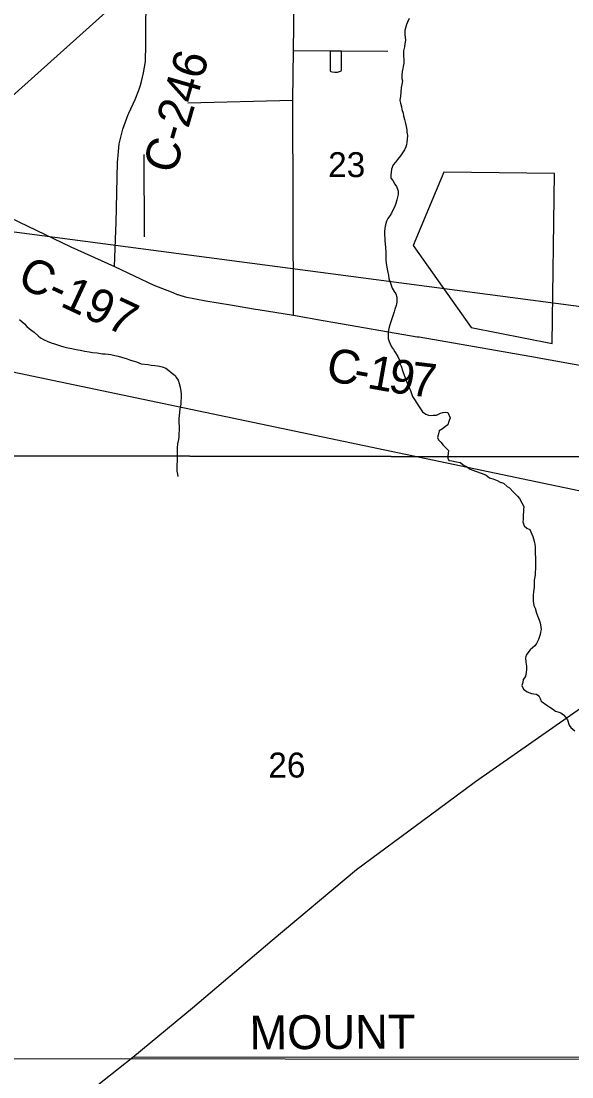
# Model space of a CAD drawing. Extents: x 0 to 34, y 0 to 22.
# Drawn here: x 6.537 to 7.462, y 15.401 to 17.171 of the extents above; entities that cross this region are included whole.
import ezdxf

# ---------------------------------------------------------------- set-up
doc = ezdxf.new("R2010")
doc.units = 0
for name, color, linetype in [('GM_X_City_Street', 7, 'Continuous'), ('GM_X_County_Road', 7, 'Continuous'), ('GM_X_County_Road_Text', 7, 'Continuous'), ('GM_X_Minor_Lake', 7, 'Continuous'), ('GM_X_Minor_River', 7, 'Continuous'), ('GM_X_Rail_Line', 7, 'Continuous'), ('GM_X_Section', 7, 'Continuous'), ('GM_X_Section_Text', 7, 'Continuous'), ('GM_X_Township_Road', 7, 'Continuous'), ('GM_X_Township_Road_Text', 7, 'Continuous'), ('SH_Data', 7, 'Continuous')]:
    doc.layers.add(name, color=color, linetype=linetype)

msp = doc.modelspace()

# ---------------------------------------------------------------- linework, layer by layer
at = {"layer": 'GM_X_City_Street'}
for p, q in [((6.817, 17.0337), (6.9929, 17.0382)), ((6.7444, 16.8095), (6.7437, 16.9474))]:
    msp.add_line(p, q, dxfattribs=at)
for points in [[(6.994, 17.1215), (7.0557, 17.1213), (7.0747, 17.1212), (7.1527, 17.1208)], [(7.0557, 17.1213), (7.0556, 17.0874), (7.0568, 17.0867), (7.0593, 17.0859), (7.0636, 17.0851), (7.068, 17.0852), (7.0733, 17.0868), (7.0741, 17.0875), (7.0746, 17.0885), (7.0747, 17.1212)]]:
    msp.add_lwpolyline(points, dxfattribs=at)
at = {"layer": 'GM_X_County_Road'}
for p, q in [((6.6936, 16.7596), (6.6961, 16.8196)), ((6.8036, 16.7112), (6.8126, 16.7084)), ((6.9943, 16.6777), (7.0438, 16.6692)), ((7.0438, 16.6692), (7.0635, 16.6658)), ((7.0635, 16.6658), (7.2021, 16.6418))]:
    msp.add_line(p, q, dxfattribs=at)
for points in [[(6.9943, 16.6777), (6.9929, 17.0382), (6.994, 17.1215), (6.9958, 17.2486), (6.9968, 17.319), (6.9978, 17.387), (7.0072, 17.472), (7, 17.5404)], [(6.7374, 17.0638), (6.7393, 17.0697), (6.7425, 17.084), (6.7456, 17.1033), (6.7462, 17.1319), (6.7464, 17.1706), (6.7473, 17.2079), (6.7515, 17.2415), (6.7604, 17.279), (6.7736, 17.3034), (6.7807, 17.3258), (6.7807, 17.3402), (6.7779, 17.3604), (6.7688, 17.3754), (6.7575, 17.3922)], [(6.6996, 16.9402), (6.7, 16.9456), (6.7016, 16.9651), (6.7078, 16.9898), (6.7168, 17.0144), (6.7178, 17.0166), (6.7283, 17.0397), (6.7345, 17.0549), (6.7374, 17.0638)], [(6.6961, 16.8196), (6.6966, 16.8329), (6.699, 16.9336), (6.6996, 16.9402)], [(6.4994, 16.8506), (6.5042, 16.8482), (6.6203, 16.7926), (6.6936, 16.7596), (6.76, 16.7284), (6.7817, 16.7198), (6.7916, 16.7158), (6.7987, 16.7128), (6.8, 16.7123), (6.8036, 16.7112)], [(6.8126, 16.7084), (6.847, 16.7019), (6.8884, 16.6952), (6.9305, 16.6882)], [(6.9305, 16.6882), (6.9351, 16.6875), (6.9943, 16.6777)], [(7.2021, 16.6418), (7.2051, 16.6413), (7.3908, 16.6094), (7.4995, 16.5896)], [(7.237, 15.8497), (7.2995, 15.8959), (7.4946, 16.032)], [(5.5469, 14.4344), (5.6758, 14.5508), (5.8694, 14.7369), (6.0097, 14.8665), (6.1246, 14.9524), (6.1906, 14.9973), (6.2946, 15.0744), (6.3669, 15.1429), (6.4394, 15.2123), (6.6285, 15.3575), (6.7245, 15.4335), (6.8246, 15.5163), (6.9585, 15.6298), (7.1001, 15.7486), (7.237, 15.8497)]]:
    msp.add_lwpolyline(points, dxfattribs=at)
at = {"layer": 'GM_X_Minor_Lake'}
for p, q in [((7.2464, 16.9179), (7.1952, 16.7947)), ((7.4322, 16.9154), (7.2464, 16.9179)), ((7.4283, 16.6306), (7.4322, 16.9154)), ((7.1952, 16.7947), (7.2924, 16.6572)), ((7.2924, 16.6572), (7.4283, 16.6306))]:
    msp.add_line(p, q, dxfattribs=at)
at = {"layer": 'GM_X_Minor_River'}
for p, q in [((7.4322, 16.9154), (7.4322, 16.9154)), ((7.1952, 16.7947), (7.1952, 16.7947)), ((7.2924, 16.6572), (7.2924, 16.6572)), ((7.4283, 16.6306), (7.4283, 16.6306))]:
    msp.add_line(p, q, dxfattribs=at)
for points in [[(7.1883, 17.1753), (7.1857, 17.1692), (7.1842, 17.1654), (7.1827, 17.1612), (7.1812, 17.1551), (7.1813, 17.1487), (7.1821, 17.1388), (7.1813, 17.1331), (7.1806, 17.1278), (7.1791, 17.1213), (7.1787, 17.1175), (7.1788, 17.1133), (7.1796, 17.1057), (7.1796, 17.1004), (7.1785, 17.0951), (7.1777, 17.0913), (7.1766, 17.0864), (7.1759, 17.0803), (7.1763, 17.0746), (7.1771, 17.0708), (7.176, 17.0647), (7.1752, 17.0594), (7.1745, 17.0514), (7.1738, 17.0453), (7.1727, 17.0377), (7.1739, 17.0335), (7.1754, 17.0271), (7.1762, 17.0229), (7.1781, 17.0165), (7.1789, 17.0119), (7.1804, 17.0062), (7.1824, 16.999), (7.1832, 16.9945), (7.1843, 16.9888), (7.1847, 16.985), (7.1855, 16.9789), (7.1852, 16.9732), (7.1844, 16.9679), (7.1837, 16.9637), (7.183, 16.9599), (7.1807, 16.9553), (7.1739, 16.945), (7.1686, 16.9389), (7.1652, 16.9344), (7.1615, 16.9302), (7.1585, 16.9225), (7.1581, 16.9176), (7.1574, 16.9127), (7.1578, 16.9077), (7.1608, 16.9039)], [(7.1608, 16.9039), (7.1643, 16.8975), (7.1673, 16.8937), (7.1697, 16.8865), (7.1701, 16.8801), (7.169, 16.8759), (7.1678, 16.8713), (7.166, 16.8652), (7.1637, 16.8591), (7.1607, 16.8527), (7.1585, 16.8488), (7.1558, 16.8447), (7.1528, 16.8397), (7.1502, 16.8355), (7.1479, 16.8271), (7.1472, 16.8188), (7.1469, 16.8127), (7.1473, 16.8066), (7.1477, 16.8028), (7.1489, 16.7918), (7.1493, 16.7831), (7.1494, 16.7698), (7.1502, 16.7611), (7.1525, 16.7497), (7.1537, 16.7451), (7.1545, 16.7394), (7.1564, 16.7334), (7.1583, 16.7284), (7.1599, 16.7231), (7.1633, 16.7174), (7.166, 16.7136), (7.1679, 16.708), (7.1679, 16.6996), (7.1665, 16.6943), (7.1646, 16.6878), (7.1635, 16.6832), (7.1597, 16.6734), (7.1579, 16.6669), (7.156, 16.6619), (7.1545, 16.6555), (7.1534, 16.6498), (7.153, 16.6441), (7.1531, 16.6388), (7.155, 16.6338), (7.1565, 16.63), (7.1585, 16.6247), (7.1619, 16.6202), (7.1642, 16.6164), (7.1692, 16.6088), (7.1715, 16.6035), (7.1734, 16.5959), (7.1749, 16.5921), (7.178, 16.5834), (7.1819, 16.5728), (7.1857, 16.5626), (7.1884, 16.5565), (7.1911, 16.5497), (7.1942, 16.5417), (7.1976, 16.5364), (7.2053, 16.5243), (7.2083, 16.5194), (7.211, 16.5156), (7.2163, 16.5118), (7.2209, 16.5103), (7.2247, 16.5099), (7.2285, 16.5103), (7.2342, 16.51), (7.241, 16.5138), (7.2452, 16.5146), (7.249, 16.515), (7.2535, 16.5146), (7.2574, 16.5059), (7.2551, 16.4994), (7.2533, 16.4941), (7.2495, 16.4911), (7.2442, 16.4872), (7.2389, 16.4838), (7.237, 16.4766), (7.2359, 16.4728), (7.2374, 16.4686), (7.2416, 16.4648), (7.2455, 16.4599), (7.2497, 16.4557), (7.2542, 16.4508), (7.2535, 16.4417), (7.2535, 16.4379), (7.2551, 16.4341), (7.26, 16.4334), (7.2676, 16.4319), (7.2741, 16.4308), (7.2805, 16.4259), (7.2844, 16.424), (7.2908, 16.4198), (7.3, 16.4161), (7.3095, 16.4131), (7.3136, 16.4112), (7.3174, 16.4097), (7.3235, 16.4052), (7.3308, 16.4029), (7.3361, 16.4007), (7.3414, 16.3981)], [(6.5342, 16.6707), (6.5426, 16.6632), (6.5468, 16.659), (6.5506, 16.6556), (6.5551, 16.6522), (6.559, 16.6492), (6.5654, 16.6435), (6.5696, 16.6401), (6.5757, 16.6367), (6.5807, 16.6345), (6.5875, 16.6315), (6.5928, 16.63), (6.5982, 16.6281), (6.6031, 16.6266), (6.6088, 16.6248), (6.6156, 16.6233), (6.6221, 16.6218), (6.6293, 16.6203), (6.6362, 16.6192), (6.6438, 16.6177), (6.651, 16.6166), (6.6571, 16.6155), (6.6647, 16.6148), (6.6738, 16.6133), (6.678, 16.6129), (6.6829, 16.6126), (6.6878, 16.6118), (6.6943, 16.6103), (6.7, 16.6092), (6.7057, 16.6077), (6.7152, 16.6044), (6.7205, 16.6025), (6.7266, 16.601), (6.7308, 16.5999), (6.7388, 16.5965), (6.7502, 16.595), (6.7555, 16.5939), (6.7616, 16.5936), (6.7657, 16.5932), (6.7695, 16.5921), (6.7737, 16.5914), (6.7798, 16.5891), (6.7848, 16.5849), (6.7889, 16.5819), (6.7954, 16.5766), (6.7981, 16.5729)], [(6.7981, 16.5729), (6.8004, 16.5691), (6.8023, 16.5634), (6.8039, 16.5569), (6.8051, 16.5501), (6.8055, 16.5459), (6.8059, 16.5395), (6.8051, 16.5338), (6.8052, 16.5288), (6.8037, 16.5208), (6.803, 16.5148), (6.8022, 16.5098), (6.8019, 16.5045), (6.8019, 16.498), (6.8023, 16.4904), (6.8023, 16.4847), (6.802, 16.4802), (6.8016, 16.4745), (6.8013, 16.4692), (6.7998, 16.4623), (6.7987, 16.4555), (6.7987, 16.449), (6.7991, 16.4452), (6.7992, 16.4407), (6.7988, 16.4334), (6.7985, 16.4266), (6.7985, 16.4163), (6.7997, 16.4114), (6.8001, 16.4076)], [(7.3414, 16.3981), (7.3467, 16.3962), (7.3528, 16.3905), (7.3567, 16.3886), (7.3628, 16.3818), (7.3704, 16.3746), (7.3738, 16.3705), (7.3777, 16.3633), (7.3807, 16.3572), (7.3804, 16.3523), (7.3804, 16.3485), (7.38, 16.3428), (7.3797, 16.3356), (7.3793, 16.3314), (7.3816, 16.3249), (7.3858, 16.3208), (7.3908, 16.3185), (7.3962, 16.3068), (7.3973, 16.303), (7.3989, 16.2969), (7.3997, 16.2901), (7.3997, 16.2844), (7.4001, 16.2794), (7.4005, 16.2699), (7.4006, 16.2631), (7.4002, 16.2525), (7.3999, 16.2471), (7.3999, 16.243), (7.3995, 16.2392), (7.3984, 16.2335), (7.3981, 16.2297), (7.3981, 16.2217), (7.397, 16.2141), (7.3967, 16.2084), (7.3967, 16.1985), (7.3975, 16.1913), (7.3998, 16.1864), (7.4021, 16.1784), (7.4052, 16.1708), (7.4079, 16.1636), (7.4087, 16.1587), (7.4099, 16.1511), (7.4091, 16.1461), (7.4084, 16.1423), (7.4054, 16.1343), (7.4024, 16.1275), (7.3994, 16.1237), (7.3952, 16.1202), (7.3914, 16.1168), (7.3877, 16.1118), (7.3846, 16.1077), (7.3839, 16.1031), (7.3843, 16.0959), (7.3851, 16.0894), (7.3851, 16.0833), (7.3848, 16.0792), (7.3837, 16.0723), (7.3799, 16.067), (7.3792, 16.0617), (7.3773, 16.0571), (7.3804, 16.0506), (7.3865, 16.0461), (7.3937, 16.0435), (7.3979, 16.0428), (7.4024, 16.0424), (7.4062, 16.0398), (7.4085, 16.0352), (7.4101, 16.0307), (7.4196, 16.0239), (7.4246, 16.0205), (7.4291, 16.0178), (7.4341, 16.0137), (7.4379, 16.0129), (7.4432, 16.0111), (7.4474, 16.008), (7.4508, 16.0039), (7.4543, 15.9993), (7.457, 15.9906), (7.46, 15.9864), (7.4665, 15.9812)]]:
    msp.add_lwpolyline(points, dxfattribs=at)
at = {"layer": 'GM_X_Rail_Line'}
msp.add_lwpolyline([(3.6815, 14.4919), (3.8612, 14.6519), (4.1651, 14.9197), (4.4686, 15.1913), (4.7768, 15.471), (5.1412, 15.8006), (5.4601, 16.0872), (6.2018, 16.7592), (6.7493, 17.2493), (7.0065, 17.4955), (7.1712, 17.6375), (7.3789, 17.8309), (7.4524, 17.8921)], dxfattribs=at)
at = {"layer": 'GM_X_Section'}
for points in [[(6.4919, 17.4489), (7.5107, 17.4428), (7.4967, 16.4401), (6.481, 16.4419)], [(6.481, 16.4419), (7.4967, 16.4401), (7.4854, 15.4301), (6.4743, 15.4308)]]:
    msp.add_lwpolyline(points, close=True, dxfattribs=at)
at = {"layer": 'GM_X_Township_Road'}
msp.add_line((6.7245, 15.4335), (7.4898, 15.4344), dxfattribs=at)
at = {"layer": 'SH_Data'}
msp.add_lwpolyline([(3.5095, 17.2146), (9.8001, 15.8963), (9.8001, 16.3863)], close=True, dxfattribs=at)

# ---------------------------------------------------------------- texts
at = {"layer": 'GM_X_County_Road_Text'}
for s, height, rotation, p in [('C-246', 0.05682, 73.8309, (6.7953, 16.9127)), ('C-197', 0.05682, 335.0307, (6.528, 16.7278)), ('C', 0.0568, 349.4827, (7.0468, 16.5688)), ('1', 0.0568, 349.9281, (7.1161, 16.556)), ('9', 0.0568, 350.7757, (7.1515, 16.5497)), ('7', 0.0568, 353.2793, (7.1887, 16.5438)), ('-', 0.0568, 349.5795, (7.0928, 16.5603))]:
    msp.add_text(s, height=height, rotation=rotation, dxfattribs=at).set_placement(p)
at = {"layer": 'GM_X_Section_Text'}
for s, p in [('23', (7.0524, 16.9093)), ('26', (6.952, 15.9026))]:
    msp.add_text(s, height=0.04186, rotation=0, dxfattribs=at).set_placement(p)
at = {"layer": 'GM_X_Township_Road_Text'}
msp.add_text('MOUNT', height=0.05682, rotation=0.3743, dxfattribs=at).set_placement((6.9206, 15.4466))

doc.saveas('drawing.dxf')
